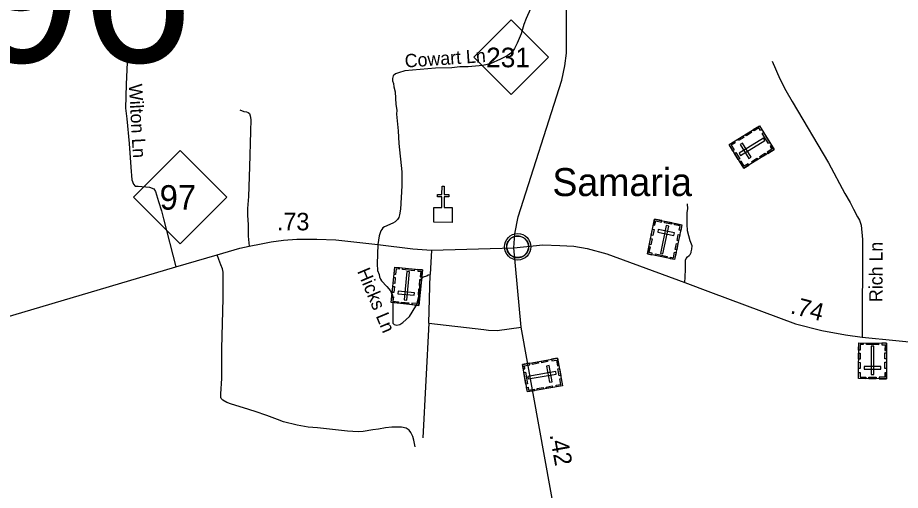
# Model space of a CAD drawing. Extents: x 2220236 to 2384410, y 720751 to 894131.
# Drawn here: x 2239863 to 2246160, y 767177 to 770552 of the extents above; entities that cross this region are included whole.
import ezdxf

# ---------------------------------------------------------------- set-up
doc = ezdxf.new("R2010")
doc.units = 0
for name, color, linetype in [('Exist Civil Demographics Community CELL', 7, 'Continuous'), ('Exist Civil Demographics Community Label', 7, 'Continuous'), ('Exist Cultural Cemetery CELL', 7, 'Continuous'), ('Exist Cultural Church CELL', 7, 'Continuous'), ('Exist Road Non-System Type 51', 7, 'Continuous'), ('Exist Road Non-System Type 51 Label', 7, 'Continuous'), ('Exist Road Primary NC Attributed', 7, 'Continuous'), ('Exist Road Primary NC Service Mileage Hundredths English Label', 7, 'Continuous'), ('Exist Road Primary NC Shield CELL', 7, 'Continuous'), ('Exist Road Primary NC Shield Number Label', 7, 'Continuous'), ('Exist Road Secondary Structure Standard Bridge Number Label', 7, 'Continuous')]:
    doc.layers.add(name, color=color, linetype=linetype)

msp = doc.modelspace()

# ---------------------------------------------------------------- linework, layer by layer
at = {"layer": 'Exist Civil Demographics Community CELL'}
msp.add_lwpolyline([(2243353.1, 768928), (2243354.1, 768933.6), (2243355.9, 768940.1), (2243358.8, 768947.3), (2243361.7, 768953.1), (2243365.1, 768958.8), (2243368.8, 768963.9), (2243372.8, 768968.3), (2243377.4, 768972.9), (2243382.9, 768977.5), (2243388.3, 768981.2), (2243393.2, 768984), (2243398.3, 768986.5), (2243403.7, 768988.8), (2243409.4, 768990.6), (2243413.7, 768991.7), (2243418.6, 768992.5), (2243422.7, 768993.2), (2243429, 768993.5), (2243433.5, 768993.4), (2243439.1, 768993.1), (2243444, 768992.4), (2243449, 768991.4), (2243454, 768990), (2243459.1, 768988), (2243465.8, 768985.1), (2243472, 768981.6), (2243477.1, 768978.1), (2243482.3, 768974.1), (2243485.6, 768970.9), (2243489.7, 768966.5), (2243493.6, 768961.8), (2243496.6, 768957.3), (2243499.8, 768952.2), (2243502.2, 768947.1), (2243504.3, 768942.1), (2243505.8, 768937.1), (2243507.1, 768932.5), (2243508.2, 768926.4), (2243508.8, 768921.7), (2243509.1, 768915.7), (2243508.9, 768909.9), (2243508.3, 768904.2), (2243507.4, 768898.8), (2243505.7, 768892.6), (2243503.9, 768886.8), (2243501.6, 768881.7), (2243498.4, 768875.7), (2243495.1, 768870.4), (2243491.7, 768865.7), (2243487.5, 768860.9), (2243482.2, 768856), (2243477.2, 768851.9), (2243472.1, 768848.4), (2243467.8, 768845.9), (2243461, 768842.7), (2243453.9, 768840), (2243447.9, 768838.5), (2243441.3, 768837.2), (2243436.9, 768836.7), (2243432.4, 768836.5), (2243426.8, 768836.5), (2243422.5, 768836.9), (2243416.9, 768837.6), (2243411, 768838.9), (2243406.4, 768840.2), (2243401.2, 768842.1), (2243396.6, 768844.1), (2243392.7, 768846.3), (2243385.9, 768850.4), (2243380.3, 768854.7), (2243375.4, 768859.2), (2243370.9, 768864), (2243367.8, 768868), (2243364.8, 768872.1), (2243360.7, 768879.2), (2243359, 768882.8), (2243357.2, 768886.8), (2243354.7, 768895), (2243353.1, 768902), (2243352.4, 768907.2), (2243352.1, 768913.5), (2243352.1, 768918.2), (2243352.6, 768924.7)], close=True, dxfattribs=at)
for centre, radius in [((2243430.7, 768915.6), 94.3), ((2243430.5, 768915.8), 76.7)]:
    msp.add_circle(centre, radius, dxfattribs=at)
at = {"layer": 'Exist Cultural Cemetery CELL'}
for points in [[(2245043.6, 769476.1), (2244938.6, 769645.2), (2245154.8, 769779.6), (2245259.9, 769610.5)], [(2245172.3, 769751.4), (2245162.6, 769745.4), (2245151, 769764.1), (2245116.6, 769742.7), (2245110.8, 769752.2), (2245154.8, 769779.6)], [(2245043.5, 769697), (2245006.7, 769674.2), (2245000.7, 769683.8), (2245037.4, 769706.7)], [(2245011, 769584.2), (2245020.9, 769568.3), (2245193.1, 769675.3), (2245183.2, 769691.2)], [(2245099.5, 769731.8), (2245062.7, 769708.9), (2245056.7, 769718.6), (2245093.4, 769741.5)], [(2245219.8, 769653.2), (2245175.1, 769725.3), (2245184.7, 769731.3), (2245229.5, 769659.2)], [(2244975.4, 769668.1), (2244981.3, 769658.5), (2244954, 769641.5), (2244975.4, 769607.1), (2244966, 769601.2), (2244938.6, 769645.3)], [(2245079.9, 769546.7), (2245095.8, 769556.5), (2245033.6, 769656.5), (2245017.8, 769646.7)], [(2245242.4, 769638.6), (2245232.7, 769632.5), (2245244.3, 769613.8), (2245210, 769592.5), (2245215.8, 769583), (2245259.9, 769610.4)], [(2245004.6, 769539), (2244977.2, 769583), (2244986.9, 769589), (2245014.3, 769545)], [(2245200.5, 769573.5), (2245163.7, 769550.7), (2245157.7, 769560.4), (2245194.5, 769583.2)], [(2245080.4, 769499), (2245074.4, 769508.6), (2245047.1, 769491.6), (2245025.7, 769526.1), (2245016.3, 769520.2), (2245043.6, 769476.1)], [(2245143.4, 769538.1), (2245106.6, 769515.2), (2245100.6, 769524.9), (2245137.4, 769547.7)], [(2244407.5, 769114.1), (2244602.4, 769073.6), (2244550.5, 768824.3), (2244355.6, 768864.9)], [(2244398.7, 769071.7), (2244409.8, 769069.4), (2244416.4, 769100.9), (2244456.1, 769092.7), (2244458.4, 769103.6), (2244407.5, 769114.1)], [(2244508.3, 769063.2), (2244490, 769067), (2244448.7, 768868.5), (2244467, 768864.7)], [(2244480, 769099), (2244530.8, 769088.5), (2244528.5, 769077.3), (2244477.7, 769087.9)], [(2244593.7, 769031.1), (2244582.6, 769033.4), (2244589.1, 769064.9), (2244549.4, 769073.2), (2244551.7, 769084.1), (2244602.5, 769073.5)], [(2244383.6, 768999.1), (2244392.4, 769041.5), (2244403.6, 769039.2), (2244394.7, 768996.8)], [(2244433.6, 769039.2), (2244429.8, 769020.9), (2244545.1, 768996.9), (2244548.9, 769015.2)], [(2244567.6, 768961.9), (2244576.4, 769004.3), (2244587.6, 769002), (2244578.8, 768959.6)], [(2244369.9, 768933.3), (2244378.7, 768975.7), (2244389.8, 768973.4), (2244381, 768931)], [(2244554.1, 768897.4), (2244563, 768939.8), (2244574.1, 768937.4), (2244565.3, 768895)], [(2244388, 768858.2), (2244390.4, 768869.4), (2244368.8, 768873.9), (2244377.1, 768913.5), (2244366.2, 768915.7), (2244355.6, 768864.9)], [(2244518.1, 768831), (2244520.5, 768842.3), (2244542, 768837.8), (2244550.2, 768877.4), (2244561.1, 768875.1), (2244550.5, 768824.3)], [(2244414.2, 768864.4), (2244497.3, 768847.1), (2244495, 768835.9), (2244411.9, 768853.2)], [(2242726.3, 768497.7), (2242528.2, 768517.4), (2242553.4, 768770.8), (2242751.5, 768751.1)], [(2242586.4, 768767.5), (2242585.2, 768756.1), (2242563.3, 768758.2), (2242559.3, 768718), (2242548.3, 768719.1), (2242553.4, 768770.8)], [(2242693.2, 768745.3), (2242608.7, 768753.7), (2242609.9, 768765.1), (2242694.3, 768756.7)], [(2242718.6, 768754.3), (2242717.4, 768742.9), (2242739.3, 768740.7), (2242735.3, 768700.5), (2242746.4, 768699.4), (2242751.5, 768751)], [(2242557.5, 768697.7), (2242553.3, 768654.6), (2242541.9, 768655.8), (2242546.2, 768698.9)], [(2242620.7, 768537.6), (2242639.3, 768535.8), (2242659.4, 768737.6), (2242640.8, 768739.4)], [(2242744.6, 768681.5), (2242740.3, 768638.4), (2242729, 768639.5), (2242733.3, 768682.6)], [(2242551, 768632.1), (2242546.7, 768589), (2242535.4, 768590.2), (2242539.7, 768633.3)], [(2242532.4, 768560.6), (2242543.7, 768559.4), (2242540.5, 768527.4), (2242580.9, 768523.4), (2242579.8, 768512.3), (2242528.1, 768517.5)], [(2242692.4, 768569.4), (2242694.3, 768588), (2242577.1, 768599.7), (2242575.2, 768581.1)], [(2242737.9, 768614.6), (2242733.7, 768571.5), (2242722.3, 768572.6), (2242726.6, 768615.7)], [(2242652.6, 768505), (2242601, 768510.2), (2242602.1, 768521.5), (2242653.7, 768516.4)], [(2242730.6, 768540.8), (2242719.3, 768541.9), (2242716.1, 768509.9), (2242675.7, 768513.9), (2242674.6, 768502.8), (2242726.3, 768497.7)], [(2246061, 767973.4), (2245861.9, 767974.4), (2245863.2, 768229.1), (2246062.3, 768228.1)], [(2245896.3, 768228.9), (2245896.3, 768217.4), (2245874.3, 768217.5), (2245874.1, 768177.1), (2245862.9, 768177.2), (2245863.2, 768229.1)], [(2246004.8, 768216.9), (2245919.9, 768217.3), (2245920, 768228.7), (2246004.8, 768228.3)], [(2245952.1, 768003.3), (2245970.8, 768003.2), (2245971.8, 768206), (2245953.1, 768206.1)], [(2246029.2, 768228.2), (2246029.2, 768216.7), (2246051.1, 768216.6), (2246050.9, 768176.2), (2246062.1, 768176.1), (2246062.3, 768228)], [(2243715.5, 768119.8), (2243750.2, 767923.8), (2243499.5, 767879.4), (2243464.8, 768075.4)], [(2243672.8, 768112.3), (2243674.8, 768101.1), (2243706.5, 768106.7), (2243713.6, 768066.8), (2243724.5, 768068.7), (2243715.5, 768119.8)], [(2245874.2, 768156.7), (2245874, 768113.4), (2245862.6, 768113.5), (2245862.8, 768156.8)], [(2246062, 768158.1), (2246061.8, 768114.8), (2246050.4, 768114.9), (2246050.6, 768158.2)], [(2243470.6, 768042.8), (2243481.9, 768044.9), (2243478.1, 768066.5), (2243517.9, 768073.6), (2243515.9, 768084.5), (2243464.8, 768075.5)], [(2243533.6, 768087.6), (2243576.3, 768095.2), (2243578.3, 768084), (2243535.6, 768076.4)], [(2243599.8, 768099.4), (2243642.5, 768106.9), (2243644.5, 768095.7), (2243601.8, 768088.1)], [(2243655.6, 768067.8), (2243637.2, 768064.5), (2243657.8, 767948.6), (2243676.1, 767951.8)], [(2245873.9, 768090.8), (2245873.6, 768047.5), (2245862.3, 768047.6), (2245862.5, 768090.9)], [(2246020.5, 768041.7), (2246020.6, 768060.4), (2245902.9, 768061), (2245902.8, 768042.3)], [(2246061.6, 768090.9), (2246061.4, 768047.6), (2246050, 768047.6), (2246050.2, 768091)], [(2243486.1, 768020.8), (2243500.9, 767937.3), (2243489.7, 767935.3), (2243474.9, 768018.8)], [(2243705.7, 768007.4), (2243702.4, 768025.8), (2243502.7, 767990.4), (2243506, 767972)], [(2243728.4, 768046.9), (2243737.4, 767995.9), (2243726.2, 767993.9), (2243717.2, 768044.9)], [(2245862.1, 768017.8), (2245873.4, 768017.7), (2245873.3, 767985.5), (2245913.8, 767985.3), (2245913.8, 767974.2), (2245861.9, 767974.5)], [(2246061.2, 768016.8), (2246049.9, 768016.8), (2246049.7, 767984.6), (2246009.2, 767984.8), (2246009.1, 767973.7), (2246061, 767973.4)], [(2243707.5, 767916.2), (2243705.6, 767927.3), (2243737.3, 767933), (2243730.2, 767972.9), (2243741.1, 767974.8), (2243750.2, 767923.7)], [(2245987, 767973.8), (2245935.1, 767974.1), (2245935.2, 767985.5), (2245987, 767985.2)], [(2243493.7, 767912), (2243505, 767914), (2243508.9, 767892.3), (2243548.7, 767899.4), (2243550.6, 767888.4), (2243499.5, 767879.4)], [(2243568.7, 767903.2), (2243611.3, 767910.7), (2243613.3, 767899.5), (2243570.7, 767892)], [(2243633.6, 767914.7), (2243676.2, 767922.2), (2243678.2, 767911), (2243635.6, 767903.4)]]:
    msp.add_lwpolyline(points, close=True, dxfattribs=at)
at = {"layer": 'Exist Cultural Church CELL'}
msp.add_lwpolyline([(2242832.9, 769197.4), (2242889.8, 769197.2), (2242890.3, 769273.3), (2242858.3, 769273.5), (2242858.4, 769289.5), (2242890.4, 769289.3), (2242890.8, 769349.4), (2242906.8, 769349.3), (2242906.4, 769289.2), (2242938.4, 769288.9), (2242938.3, 769273), (2242906.3, 769273.2), (2242905.8, 769197), (2242963.5, 769196.5), (2242962.7, 769090.1), (2242832.1, 769091)], close=True, dxfattribs=at)
at = {"layer": 'Exist Road Non-System Type 51'}
for p, q in [((2242816.7, 768892.5), (2242807.2, 768717.3)), ((2242796.1, 768371.4), (2242807.2, 768717.3)), ((2242796.1, 768371.4), (2242752.9, 767551.3))]:
    msp.add_line(p, q, dxfattribs=at)
for points in [[(2243521.6, 770614.3), (2243490.1, 770546.2), (2243474.5, 770501.9), (2243455, 770435.9), (2243427.6, 770369.7), (2243407.9, 770331.5), (2243388.1, 770303.4), (2243356.4, 770279.2), (2243308.5, 770254.8), (2243234.9, 770222.1), (2243181, 770209.8), (2243077.1, 770201), (2243017.1, 770200.4), (2242961.2, 770194), (2242843.3, 770191), (2242625.6, 770171.3), (2242579.7, 770158.8), (2242557.8, 770150.7), (2242541.9, 770136.6), (2242538.1, 770116.5), (2242538.1, 770100.5), (2242544.3, 770080.6), (2242546.5, 770058.7), (2242556.7, 770022.7), (2242561.5, 769932.8), (2242567.8, 769890.9), (2242566.1, 769863), (2242577, 769743), (2242581.7, 769653.1), (2242603.4, 769451.3), (2242604.3, 769351.3), (2242593.5, 769185.4), (2242588, 769143.3), (2242582.1, 769125.4), (2242574.2, 769111.2), (2242556.3, 769095.2), (2242540.5, 769085.1), (2242480.7, 769058.5), (2242468.8, 769050.4), (2242460.8, 769040.3), (2242455, 769030.3), (2242443.2, 768994.3), (2242433.7, 768932.1)], [(2240673.3, 770319.1), (2240645.5, 770234.1), (2240638.6, 770074.6), (2240631.7, 769904.6), (2240642.1, 769828.3), (2240659.4, 769653.1), (2240669.8, 769484.9), (2240678.5, 769393), (2240688.9, 769361.8), (2240702.7, 769349.6), (2240723.5, 769347.9), (2240805, 769341), (2240834.4, 769330.6), (2240846.6, 769311.5), (2240869.1, 769240.4), (2240889.9, 769172.7), (2240903.8, 769115.5), (2240991.9, 768772.1)], [(2245245.9, 770240.6), (2245300.9, 770115.1), (2245343.6, 770031.4), (2245388.2, 769953.9), (2245648.2, 769515.2), (2245763.3, 769295.2), (2245801.9, 769232.2), (2245825.2, 769184.3), (2245855.6, 769129.1), (2245870.1, 769105.9), (2245880.3, 769069.6), (2245890.4, 768968), (2245889, 768269.9)], [(2241447.4, 769892.6), (2241476.4, 769882.4), (2241495.3, 769879.5), (2241508.3, 769875.2), (2241517, 769866.5), (2241522.8, 769850.5), (2241527.2, 769824.4), (2241525.7, 769738.7), (2241517, 769487.6), (2241511.2, 769275.7), (2241504, 769190.1), (2241502.5, 769140.7), (2241506.9, 769072.5), (2241508.3, 768992.7), (2241515.4, 768919.7)], [(2244622.8, 768660.2), (2244625.6, 768699.5), (2244628.5, 768756.1), (2244627, 768796.8), (2244628.5, 768821.4), (2244632.8, 768831.6), (2244641.5, 768844.6), (2244654.6, 768854.8), (2244660.4, 768860.6), (2244669.1, 768875.1), (2244669.1, 768879.5), (2244673.4, 768898.4), (2244674.9, 768923), (2244660.4, 768957.9), (2244643, 769029), (2244640.1, 769076.9), (2244638.6, 769123.3), (2244640.1, 769161.1), (2244644.4, 769187.2), (2244643, 769223.5)], [(2242433.7, 768932.1), (2242430.3, 768862.2), (2242428.9, 768794.3), (2242431.3, 768746.2), (2242441.5, 768718.4), (2242445.6, 768700.3), (2242451.6, 768684.4), (2242459.8, 768672.5), (2242498.2, 768632.9), (2242524.3, 768601.1), (2242530.5, 768583.2), (2242536.7, 768571.1), (2242538.9, 768543.3), (2242540.2, 768371.3), (2242548.4, 768361.3), (2242568.4, 768355.5), (2242590.4, 768361.6), (2242612.3, 768375.8), (2242657.9, 768418.2), (2242705.2, 768492.7), (2242715, 768512.6), (2242716.9, 768524.6), (2242726.6, 768560.8), (2242732.1, 768630.7), (2242731.8, 768666.7), (2242733.8, 768674.8), (2242743.6, 768686.8), (2242759.5, 768700.9), (2242781.5, 768709), (2242791.4, 768715.2), (2242807.2, 768717.3)], [(2242699.2, 767487.5), (2242690.5, 767535.4), (2242683.3, 767561.6), (2242668.8, 767589.1), (2242655.7, 767606.5), (2242635.4, 767621.1), (2242600.6, 767628.3), (2242565.8, 767628.3), (2242532.4, 767626.9), (2242487.5, 767622.5), (2242438.1, 767613.8), (2242397.5, 767608), (2242327.9, 767596.4), (2242293.1, 767593.5), (2242216.2, 767599.3), (2242172.7, 767605.1), (2242001.5, 767622.5), (2241936.3, 767628.3), (2241857.9, 767641.4), (2241759.3, 767666.1), (2241717.2, 767683.5), (2241641.8, 767711.1), (2241557.7, 767740.1), (2241475, 767766.2), (2241389.4, 767792.3), (2241356, 767803.9), (2241327, 767819.9), (2241315.4, 767831.5), (2241314, 767840.2), (2241312.5, 767864.9), (2241319.8, 767975.2), (2241321.2, 768158.1), (2241321.2, 768190), (2241328.5, 768547.1), (2241329.9, 768689.3), (2241328.5, 768735.8), (2241324.1, 768757.6), (2241312.5, 768788), (2241299.5, 768824.3), (2241286.5, 768858.8)], [(2242796.1, 768371.4), (2243188.2, 768324.6), (2243222.4, 768320.9), (2243284.3, 768317.4), (2243456.1, 768342.8)]]:
    msp.add_lwpolyline(points, dxfattribs=at)
at = {"layer": 'Exist Road Primary NC Attributed'}
for points in [[(2243404.2, 768908.5), (2243410, 769007.2), (2243433.2, 769129.1), (2243746.5, 770104.5), (2243766.8, 770207.6), (2243778.1, 770298.5), (2243779.9, 770888.3), (2243782.4, 771111.2)], [(2239633.6, 768371.7), (2240991.9, 768772.1), (2241286.5, 768858.8), (2241447.4, 768905.6), (2241515.4, 768919.7), (2241601.2, 768937.5), (2241672.3, 768952.1), (2241760.7, 768963.7), (2241855, 768970.9), (2241998.6, 768970.9), (2242133.5, 768966.6), (2242433.7, 768932.1), (2242683.3, 768901.3), (2242816.7, 768892.5), (2243404.2, 768908.5)], [(2243404.2, 768908.5), (2243610.2, 768928.8), (2243732, 768924.5), (2243830.7, 768920.1), (2243927.4, 768904.4), (2244065.7, 768866.4), (2244622.8, 768660.2), (2244806.9, 768592.1), (2245412.9, 768366.8), (2245599.2, 768318.2), (2245769.6, 768287.7), (2245889, 768269.9), (2246369.1, 768222), (2246940.6, 768169.7), (2247148.1, 768147.9), (2247220.6, 768137.8)], [(2243752.3, 766697.9), (2243456.1, 768342.8), (2243404.2, 768908.5)]]:
    msp.add_lwpolyline(points, dxfattribs=at)
at = {"layer": 'Exist Road Primary NC Shield CELL'}
for points in [[(2243118.4, 770269.4), (2243384.8, 770535.8), (2243651.2, 770269.4), (2243384.8, 770003)], [(2240689.1, 769270.6), (2241022.1, 769603.6), (2241355.1, 769270.6), (2241022.1, 768937.6)]]:
    msp.add_lwpolyline(points, close=True, dxfattribs=at)

# ---------------------------------------------------------------- texts
at = {"layer": 'Exist Civil Demographics Community Label'}
msp.add_text('Samaria', height=200, dxfattribs=at).set_placement((2243678.1, 769277.9))
at = {"layer": 'Exist Road Non-System Type 51 Label'}
for s, rotation, p in [('Cowart Ln', 3.95851, (2242627.9, 770195.1)), ('Wilton Ln', 273.21613, (2240656.5, 770076.3)), ('Rich Ln', 89.89506, (2246033.1, 768520.9)), ('Hicks Ln', 292.69906, (2242283.5, 768741.5))]:
    msp.add_text(s, height=95, rotation=rotation, dxfattribs=at).set_placement(p)
at = {"layer": 'Exist Road Primary NC Service Mileage Hundredths English Label'}
msp.add_text('.73', height=125, dxfattribs=at).set_placement((2241712.2, 769033.4))
for s, rotation, p in [('.74', 345.37642, (2245370.4, 768442.5)), ('.42', 280.20719, (2243658.1, 767573.7))]:
    msp.add_text(s, height=125, rotation=rotation, dxfattribs=at).set_placement(p)
at = {"layer": 'Exist Road Primary NC Shield Number Label'}
for s, height, p in [('231', 140, (2243205.7, 770197.6)), ('97', 175, (2240876.2, 769180.9))]:
    msp.add_text(s, height=height, dxfattribs=at).set_placement(p)
at = {"layer": 'Exist Road Secondary Structure Standard Bridge Number Label'}
msp.add_text('96', height=1066.27, dxfattribs=at).set_placement((2239525.7, 770233.4))

doc.saveas('drawing.dxf')
